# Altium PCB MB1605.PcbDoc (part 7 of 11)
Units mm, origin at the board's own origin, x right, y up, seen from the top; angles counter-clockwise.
Board outline 100 x 79.6 mm, 6 copper layers (Top Layer, Signal Layer 1, Signal Layer 2, Signal Layer 3, Signal Layer 4, Bottom Layer), stack 1.549 mm thick; 644 components, 529 nets, 2853 pads, 1462 vias.
Unrouted connection lines stored in the file: 2.
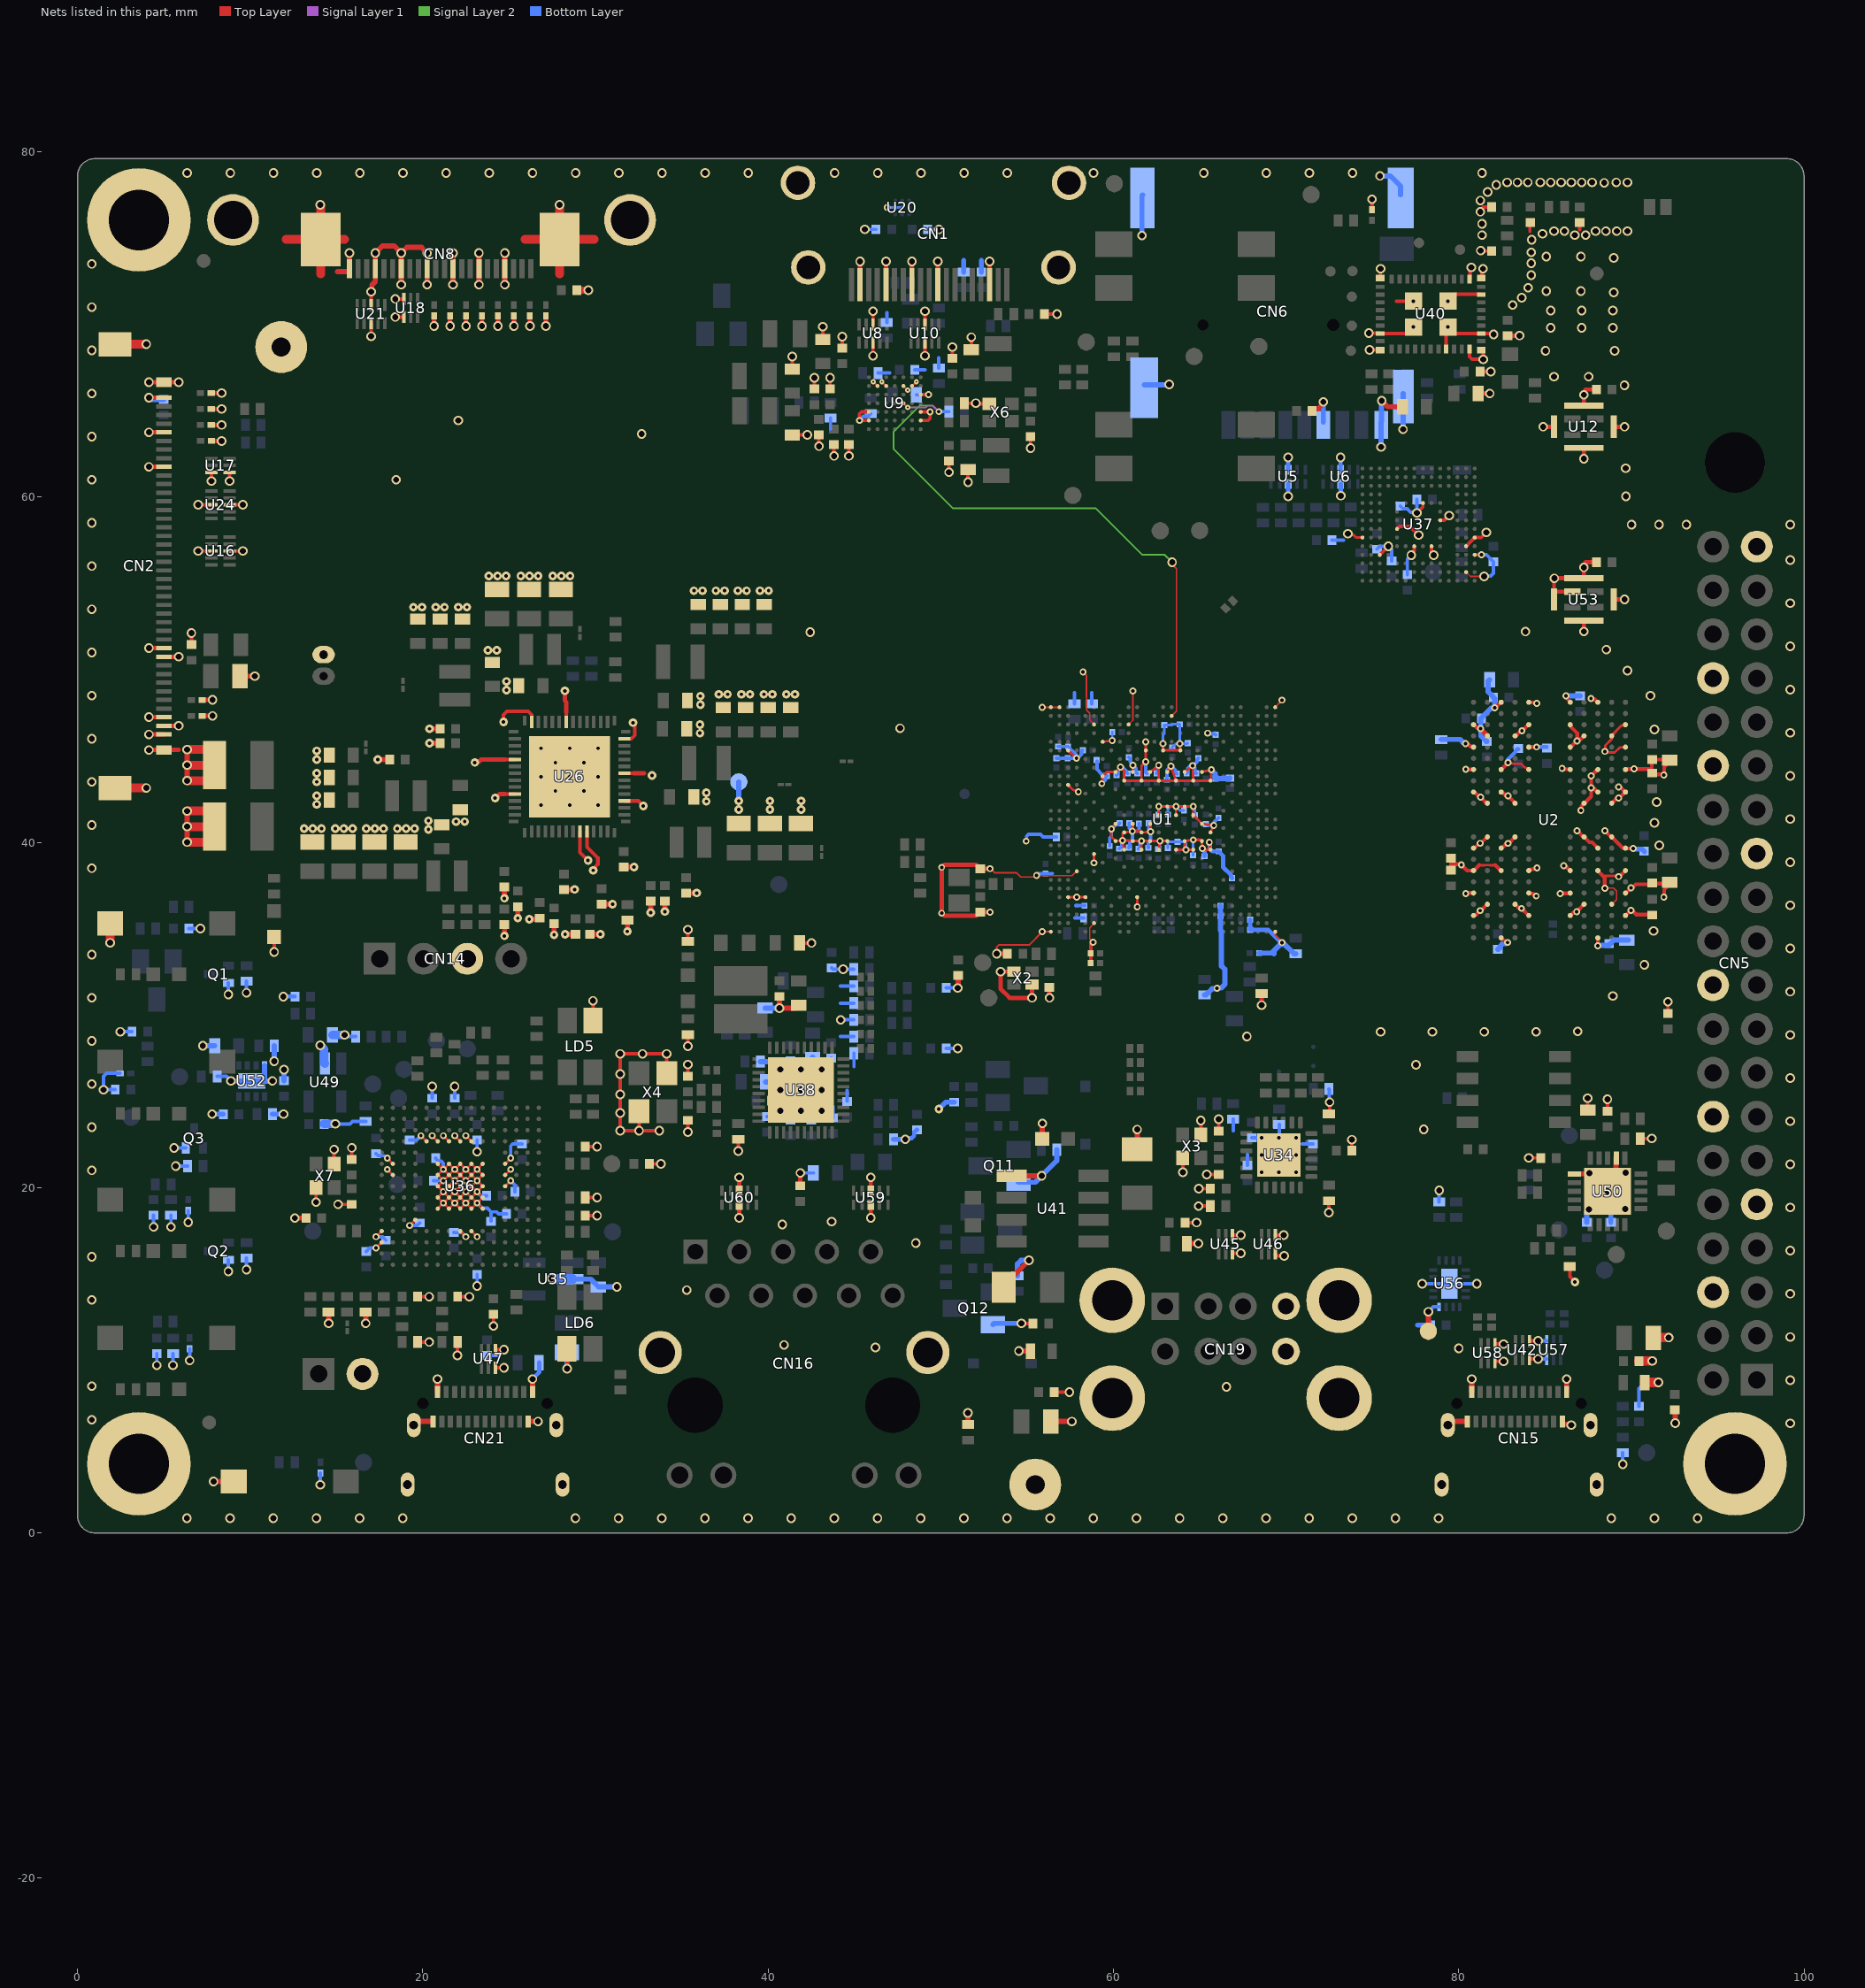
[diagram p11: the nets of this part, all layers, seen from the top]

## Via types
v1: diameter 0.55, hole 0.35, Top Layer to Bottom Layer, 823 vias
v2: diameter 0.4, hole 0.2, Top Layer to Bottom Layer, 235 vias
v3: diameter 0.4, hole 0.2, Top Layer to Bottom Layer, tented both sides, 216 vias
v4: diameter 0.5, hole 0.2, Top Layer to Bottom Layer, 159 vias
v5: diameter 0.25/0.3 (per signal layer), hole 0.1, Top Layer to Signal Layer 1, tented both sides, 29 vias

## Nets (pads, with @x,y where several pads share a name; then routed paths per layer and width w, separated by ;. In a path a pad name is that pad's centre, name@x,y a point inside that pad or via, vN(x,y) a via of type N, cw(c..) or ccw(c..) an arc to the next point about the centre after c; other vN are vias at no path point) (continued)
GND: B1.2 B2.1 C1.1 C2.1 C3.1 C4.2 C5.2 C6.2 C7.2 C8.2 C9.1 C10.1 C11.1 C12.2 C13.2 C14.2 C15.2 C16.2 C17.2 C18.2 C19.2 C20.2 C21.2 C22.1 C23.1 C24.1 C25.1 C26.1 C27.1 C28.1 C29.1 C30.1 C31.2 C32.1 C33.1 C34.1 C35.1 C36.1 C37.1 C38.1 C39.1 C40.1 C41.1 C42.2 C43.1 C44.2 C45.1 C46.1 C47.2 C48.1 C49.1 C50.1 C51.1 C52.1 C53.1 C54.1 C55.1 C56.1 C57.1 C58.1 C59.1 C60.1 C61.1 C62.2 C63.1 C64.1 C65.2 C66.1 C67.1 C68.1 C69.1 C70.2 C71.1 C72.1 C73.2 C74.1 C75.1 C76.1 C77.2 C78.2 C79.2 C80.2 C81.2 C82.1 C83.1 C84.1 C85.1 C86.2 C87.1 C88.1 C89.1 C90.1 C91.2 C92.2 C93.1 C96.2 C97.2 C98.2 C99.2 C101.1 C102.2 C103.1 C104.1 C105.2 C106.2 C107.2 C108.1 C109.1 C110.1 C111.1 C113.1 C114.1 C115.1 C116.1 C117.1 C118.1 C119.1 C120.1 C122.1 C123.1 C125.1 C126.1 C127.1 C128.1 C129.1 C130.1 C131.1 C132.1 C133.1 C134.1 C135.1 C136.1 C137.1 C139.1 C140.2 C141.1 C143.1 C145.1 C146.1 C147.2 C148.1 C149.1 C150.1 C151.1 C152.1 C155.1 C156.1 C157.2 C158.2 C159.1 C160.1 C161.1 C162.1 C163.1 C164.2 C165.1 C166.1 C167.1 C168.1 C169.1 C170.1 C171.1 C172.1 C173.1 C174.1 C175.1 C176.1 C177.1 C179.1 C180.1 C181.1 C182.1 C183.1 C184.1 C185.1 C186.1 C187.1 C188.1 C189.1 C190.2 C192.1 C193.1 C194.1 C195.1 C196.1 C197.1 C198.1 C199.1 C200.1 C201.1 C202.1 C203.1 C204.1 C205.1 C206.1 C207.1 C208.2 C209.1 C213.1 C214.2 C215.2 C216.1 C217.2 C218.1 C219.1 C220.1 C222.1 C223.1 C224.1 C225.1 C226.1 C227.1 C228.2 C229.2 C232.2 C233.1 C234.1 C235.1 C236.1 C237.1 C238.1 C239.1 C240.1 C244.1 C246.1 C248.1 C250.1 C251.1 C252.1 C253.1 C260.1 C280.2 C281.2 C282.2 C288.1 C289.2 C290.2 C295.1 C296.1 C297.2 C298.2 C299.2 C302.1 C303.2 C306.1 C309.1 C310.2 C311.2 C314.1 C317.1 C322.1 C323.1 C324.2 C325.2 C326.2 C327.2 C328.2 C329.2 C332.1 C333.2 C334.2 C335.2 CN1.2 CN1.5 CN1.8 CN1.11 CN1.17 CN1.20 CN1.21 CN1.22 CN1.23 CN2.1 CN2.5 CN2.9 CN2.30 CN2.31 CN2.38 CN2.39 CN2.40 CN2.41 CN2.42 CN2.43 CN2.44 CN5.6 CN5.9 CN5.14 CN5.20 CN5.25 CN5.30 CN5.34 CN5.39 CN6.6 CN6.9 CN6.11 CN6.12 CN6.13 CN6.14 CN8.1 CN8.4 CN8.7 CN8.10 CN8.13 CN8.16 CN8.19 CN8.S1 CN8.S2 CN12.2 CN14.3 CN15.A1 CN15.A12 CN15.B1 CN15.B12 CN15.SH1 CN15.SH2 CN15.SH3 CN15.SH4 CN16.15 CN16.16 CN19.B4 CN19.CH1 CN19.CH2 CN19.CH3 CN19.CH4 CN19.T4 CN21.A1 CN21.A12 CN21.B1 CN21.B12 CN21.SH1 CN21.SH2 CN21.SH3 CN21.SH4 JP3.2 LD4.2 LD5.3 LD6.3 LD11.2 pad.1@3.55,4 pad.1@3.55,76.05 pad.1@9,76.05 pad.1@32,76.05 pad.1@96,4 Q1.2 Q2.2 Q3.2 Q11.2 Q12.2 R1.1 R5.1 R6.2 R7.2 R15.2 R16.1 R17.1 R18.1 R23.2 R25.2 R26.1 R41.1 R42.1 R57.1 R97.1 R98.1 R99.1 R102.1 R106.1 R113.1 R128.1 R135.1 R137.1 R140.2 R141.1 R143.1 R151.2 R158.1 R194.2 R199.2 R200.1 R205.2 R213.2 R215.2 R220.1 R221.2 R222.2 R226.1 R229.1 R231.2 R234.1 R239.1 R242.2 R250.2 R251.2 R292.1 R293.1 R303.1 R304.1 R305.1 R322.1 R323.1 R324.1 R327.1 TP8.1 TP30.1 TP34.1 TP2000.1 U1.1A1 U1.1A3 U1.1A5 U1.1A7 U1.1A9 U1.1A11 U1.1B2 U1.1B4 U1.1B6 U1.1B8 U1.1B10 U1.1B12 U1.1E7 U1.1E9 U1.1F6 U1.1F8 U1.1F10 U1.1G1 U1.1G3 U1.1G5 U1.1G11 U1.1H2 U1.1H4 U1.1H12 U1.1J1 U1.1J3 U1.1J5 U1.1J7 U1.1J9 U1.1J11 U1.1K2 U1.1K4 U1.1K6 U1.1K8 U1.1K10 U1.1K12 U1.A1 U1.A2 U1.A27 U1.AC3 U1.AC5 U1.AC11 U1.AF6 U1.AG1 U1.AG27 U1.C6 U1.C10 U1.E7 U1.F3 U1.F12 U1.F14 U1.F16 U1.J7 U1.K3 U1.V6 U1.Y4 U2.A3 U2.A10 U2.AB3 U2.AB5 U2.AB8 U2.AB10 U2.C1 U2.C5 U2.C8 U2.C12 U2.D2 U2.D4 U2.D9 U2.D11 U2.E1 U2.E5 U2.E8 U2.E12 U2.G1 U2.G3 U2.G5 U2.G8 U2.G10 U2.G12 U2.J1 U2.J3 U2.J10 U2.J12 U2.K2 U2.K4 U2.K9 U2.K11 U2.N2 U2.N4 U2.N9 U2.N11 U2.P1 U2.P3 U2.P10 U2.P12 U2.T1 U2.T3 U2.T5 U2.T8 U2.T10 U2.T12 U2.V1 U2.V5 U2.V8 U2.V12 U2.W2 U2.W4 U2.W9 U2.W11 U2.Y1 U2.Y5 U2.Y8 U2.Y12 U3.2 U4.2 U5.3 U5.8 U6.3 U6.8 U7.2 U8.3 U8.8 U9.B2 U9.B3 U9.B5 U9.B6 U9.C7 U9.E1 U9.E7 U9.F1 U9.F7 U10.3 U10.8 U11.2 U12.5 U13.2 U14.2 U15.2 U16.3 U16.8 U17.3 U17.4 U18.3 U18.4 U19.2 U20.B2 U20.C2 U21.3 U21.8 U22.2 U23.2 U24.3 U24.8 U25.2 U26.9 U26.10 U26.18 U26.22 U26.27 U26.36 U26.41 U26.47 U26.52 U26.57 U27.2 U28.2 U29.2 U31.2 U32.2 U33.2 U34.25 U35.2 U36.D5 U36.D6 U36.D7 U36.D8 U36.D9 U36.F2 U36.F6 U36.F7 U36.F8 U36.F9 U36.F10 U36.F12 U36.G2 U36.G6 U36.G7 U36.G8 U36.G9 U36.G10 U36.G12 U36.H6 U36.H7 U36.H8 U36.H9 U36.H10 U36.H12 U36.J6 U36.J7 U36.J8 U36.J9 U36.J10 U36.K6 U36.K7 U36.K8 U36.K9 U36.K10 U36.L4 U36.M1 U36.M8 U36.M9 U36.N1 U37.A6 U37.C4 U37.E7 U37.G5 U37.H10 U37.J5 U37.K8 U37.N2 U37.N5 U37.P4 U37.P6 U38.41 U39.2 U40.1 U40.12 U40.19 U40.21 U40.29 U40.32 U40.33 U40.35 U40.40 U40.42 U40.43 U40.44 U40.45 U40.46 U41.1 U42.3 U42.4 U43.2 U44.2 U45.3 U45.4 U46.3 U46.4 U47.3 U47.4 U48.2 U49.2 U50.12 U50.16 U50.21 U51.2 U52.8 U52.9 U53.2 U53.5 U54.2 U56.3 U56.12 U56.18 U56.19 U57.3 U57.4 U58.3 U58.4 U59.3 U59.8 U60.3 U60.8 X2.2 X2.4 X3.2 X3.4 X4.2 X4.4 X6.2 X7.2 X7.4 | length 597.6
  Top Layer w0.09: v2(55.55,38.085) 55.565,38.07 56.266,38.07 56.271,38.075 57.612,38.075 57.862,38.325 U1.Y4@57.875,38.325 ; U1.A1@56.375,47.825 U1.A2@56.875,47.825 ; 58.445,48.418 58.445,47.647 58.625,47.467 58.625,47.075 U1.C6@58.875,46.825 ; v2(58.816,34.213) 58.625,34.404 58.625,35.05 58.875,35.3 U1.AF6@58.875,35.325 ; U1.C10@60.875,46.825 61.125,47.075 v2(61.125,48.775) ; U37.N2@80.425,55.655 80.675,55.405 v1(81.475,55.405) ; U2.T10@82.459,44.194 U2.T10@82.459,44.206 ; v2@82.859,44.607 82.859,44.619 v2@82.937,44.619 ; v2@86.859,40.669 86.872,40.669 v2@86.884,40.669 ; U2.K4@87.234,40.319 U2.K4@87.259,40.319 ; v2@88.459,37.344 88.467,37.352 88.976,37.352 89.145,37.183 89.145,36.68 U2.D2@88.859,36.394
  Top Layer w0.1: v2(52.85,38.475) 52.882,38.475 53.114,38.244 54.372,38.244 54.622,37.994 55.458,37.994 v2(55.55,38.085) ; v1(53.242,33.546) 53.242,33.945 53.355,34.058 55.108,34.058 v3(55.875,34.825) U1.AG1@56.375,34.825 ; v3(55.875,47.825) U1.A1@56.375,47.825 ; v2(58.24,49.865) 58.445,49.66 58.445,48.418 ; U1.AG27@69.37,34.82 69.37,34.64 69.768,34.241 v2(69.768,34.197) ; U1.A27@69.375,47.825 69.762,48.213 v3(69.762,48.238) ; v2(83.66,46.465) 83.685,46.465 v2@83.723,46.503 ; U2.Y8@84.035,46.815 U2.Y8@84.06,46.815 ; U2.V8@84.06,45.515 84.064,45.519 U2.V8@84.084,45.519 ; v2@84.505,45.519 v2(84.509,45.523)
  Top Layer w0.125: v2@82.974,44.57 83.12,44.57 83.144,44.545 83.616,44.545 83.835,44.326 83.9,44.326 84.018,44.208 U2.T8@84.018,44.194
  Top Layer w0.13: v5(46.086,66.685) U9.B2@46.336,66.435 ; v5(46.586,66.685) U9.B3@46.836,66.435 ; U9.B5@47.836,66.435 v5(48.086,66.185) ; U9.B6@48.336,66.435 v5(48.586,66.685)
  Top Layer w0.15: v3(17.29,16.507) U36.N1@17.615,16.832 ; v3(17.29,17.157) U36.M1@17.615,17.482 ; v3(17.94,21.057) U36.G2@18.265,20.732 ; v3(17.94,21.707) U36.F2@18.265,21.382 ; v3(19.24,17.807) U36.L4@19.565,18.132 ; v3(19.89,23.007) U36.D5@20.215,22.682 ; v3(20.54,23.007) U36.D6@20.865,22.682 ; U36.K6@20.865,18.782 v3(21.19,19.107) ; U36.F6@20.865,21.382 v3(21.19,21.057) ; v3(21.19,23.007) U36.D7@21.515,22.682 ; v3(21.84,23.007) U36.D8@22.165,22.682 ; U36.M8@22.165,17.482 v3(22.49,17.157) ; v3(22.49,23.007) U36.D9@22.815,22.682 ; U36.M9@22.815,17.482 v3(23.14,17.157) ; U36.K10@23.465,18.782 v3(23.14,19.107) ; U36.F10@23.465,21.382 v3(23.14,21.057) ; U36.H12@24.765,20.082 v3(25.09,20.407) ; U36.G12@24.765,20.732 v3(25.09,21.057) ; U36.F12@24.765,21.382 v3(25.09,21.707) ; U1.AC3@57.375,36.825 v3(57.875,36.825) U1.AC5@58.375,36.825 ; U1.K3@57.375,43.325 57.643,43.057 v3(57.966,42.92) ; U1.F3@57.375,45.325 v3(57.862,44.875) ; v3(58.868,38.812) 58.875,38.819 U1.V6@58.875,39.325 ; v3@59.325,43.275 59.35,43.3 59.35,43.613 ; v3(59.325,43.4) 59.35,43.613 ; U1.E7@59.375,45.825 v3(59.931,45.892) ; U1.J7@59.388,43.812 U1.J7@59.375,43.825 ; v3@59.862,40.821 v3(59.884,40.766) ; U1.1G1@60.125,41.075 v3(59.884,40.766) ; U1.1K2@60.625,39.575 v3(60.525,40.1) ; U1.1G3@61.125,41.075 v3(61.092,40.638) ; U1.1A3@61.125,44.075 v3(61.132,44.466) ; v3(61.375,36.265) U1.AC11@61.375,36.825 ; U1.1K4@61.625,39.575 v3(61.625,40.089) ; v3(61.875,45.825) U1.F12@61.875,45.325 v3(61.875,44.675) 61.625,44.425 U1.1B4@61.625,43.575 ; U1.1G5@62.125,41.075 v3(62.15,40.625) U1.1H4@61.625,40.575 61.562,40.638 v3(61.092,40.638) ; U1.1A5@62.125,44.075 v3(62.622,44.455) U1.1B6@62.625,43.575 ; U1.1K6@62.625,39.575 v3(62.7,40.075) ; U1.1F6@62.637,41.587 U1.1F6@62.625,41.575 ; v3(62.875,45.725) U1.F14@62.875,45.325 U1.F16@63.875,45.325 v3@63.853,45.725 ; U1.1J7@63.125,40.075 v3(62.7,40.075) ; U1.1A7@63.125,44.075 v3(63.328,44.412) U1.1B8@63.625,43.575 ; U1.1E7@63.137,42.062 U1.1E7@63.125,42.075 ; U1.1K8@63.625,39.575 v3(64.198,39.575) U1.1K10@64.625,39.575 ; U1.1F8@63.625,41.575 v3(63.625,42.075) ; U1.1A9@64.125,44.075 v3(64.586,44.446) U1.1B10@64.625,43.575 ; U1.1A11@65.125,44.075 v3(65.675,44.2) U1.1B12@65.625,43.575 U1.1B10@64.625,43.575 ; U1.1H12@65.625,40.575 v3(65.806,40.972) U1.1G11@65.125,41.075 U1.1F10@64.625,41.575 v3(64.625,42.075) U1.1E9@64.125,42.075 v3(63.625,42.075) ; v1(73.575,57.875) 73.646,57.804 73.911,57.804 74.056,57.66 74.42,57.66 U37.A6@74.425,57.655 ; U37.P4@80.925,56.655 v2(81.325,56.655) ; 81.193,38.681 81.527,38.681 81.531,38.684 81.791,38.684 81.795,38.681 82.106,38.681 ; v2@82.937,44.619 82.937,44.609 82.974,44.572 v2@82.974,44.57 ; U2.T8@84.018,44.194 U2.T8@84.059,44.194 ; 88.348,38.055 88.724,38.055 88.729,38.05 89.228,38.05 v2@89.259,38.019 ; U2.W2@88.859,46.169 88.859,46.196 89.433,46.77 89.562,46.77 U2.Y1@89.608,46.816 ; U2.W2@88.86,46.168 88.843,46.151 88.843,45.957 88.495,45.609 88.495,45.298 88.45,45.253 88.486,45.217 88.711,45.217 88.729,45.2 89.033,45.2 89.334,45.501 U2.V1@89.652,45.501 ; v3(21.19,19.107) U36.J7@21.515,19.432 ; v3(21.19,19.107) U36.J6@20.865,19.432 v3(21.19,19.757) ; v3(21.19,19.107) U36.K7@21.515,18.782 v3(21.84,19.107) ; v3(21.19,19.757) U36.H7@21.515,20.082 ; v3(21.19,19.757) U36.H6@20.865,20.082 v3(21.19,20.407) ; v3(21.19,19.757) U36.J7@21.515,19.432 ; v3(21.19,20.407) U36.G7@21.515,20.732 ; v3(21.19,20.407) U36.G6@20.865,20.732 v3(21.19,21.057) ; v3(21.19,20.407) U36.H7@21.515,20.082 ; v3(21.19,21.057) U36.F7@21.515,21.382 v3(21.84,21.057) ; v3(21.19,21.057) U36.G7@21.515,20.732 ; U36.J7@21.515,19.432 v3(21.84,19.757) ; U36.J7@21.515,19.432 v3(21.84,19.107) ; U36.H7@21.515,20.082 v3(21.84,20.407) ; U36.H7@21.515,20.082 v3(21.84,19.757) ; U36.G7@21.515,20.732 v3(21.84,21.057) ; U36.G7@21.515,20.732 v3(21.84,20.407) ; v3(21.84,19.107) U36.J8@22.165,19.432 ; v3(21.84,19.107) U36.K8@22.165,18.782 v3(22.49,19.107) ; v3(21.84,19.757) U36.H8@22.165,20.082 ; v3(21.84,19.757) U36.J8@22.165,19.432 ; v3(21.84,20.407) U36.G8@22.165,20.732 ; v3(21.84,20.407) U36.H8@22.165,20.082 ; v3(21.84,21.057) U36.F8@22.165,21.382 v3(22.49,21.057) ; v3(21.84,21.057) U36.G8@22.165,20.732 ; U36.J8@22.165,19.432 v3(22.49,19.757) ; U36.J8@22.165,19.432 v3(22.49,19.107) ; U36.H8@22.165,20.082 v3(22.49,20.407) ; U36.H8@22.165,20.082 v3(22.49,19.757) ; U36.G8@22.165,20.732 v3(22.49,21.057) ; U36.G8@22.165,20.732 v3(22.49,20.407) ; v3(22.49,19.107) U36.J9@22.815,19.432 ; v3(22.49,19.107) U36.K9@22.815,18.782 v3(23.14,19.107) ; v3(22.49,19.757) U36.H9@22.815,20.082 ; v3(22.49,19.757) U36.J9@22.815,19.432 ; v3(22.49,20.407) U36.G9@22.815,20.732 ; v3(22.49,20.407) U36.H9@22.815,20.082 ; v3(22.49,21.057) U36.F9@22.815,21.382 v3(23.14,21.057) ; v3(22.49,21.057) U36.G9@22.815,20.732 ; U36.J9@22.815,19.432 v3(23.14,19.757) ; U36.J9@22.815,19.432 v3(23.14,19.107) ; U36.H9@22.815,20.082 v3(23.14,20.407) ; U36.H9@22.815,20.082 v3(23.14,19.757) ; U36.G9@22.815,20.732 v3(23.14,21.057) ; U36.G9@22.815,20.732 v3(23.14,20.407) ; v3(23.14,19.107) U36.J10@23.465,19.432 v3(23.14,19.757) ; v3(23.14,19.757) U36.H10@23.465,20.082 v3(23.14,20.407) ; v3(23.14,20.407) U36.G10@23.465,20.732 v3(23.14,21.057) ; 59.35,43.613 59.35,43.825 U1.J7@59.375,43.825 ; 59.35,43.613 U1.J7@59.375,43.825 ; U1.J7@59.375,43.825 59.625,44.075 U1.1A1@60.125,44.075 60.133,44.075 60.408,44.35 v3(60.408,44.353) 60.625,44.136 U1.1B2@60.625,43.575 U1.1B4@61.625,43.575 ; v3(59.884,40.766) 59.884,40.316 U1.1J1@60.125,40.075 v3(60.525,40.1) ; v3(60.525,40.1) 60.525,40.475 U1.1H2@60.625,40.575 v3(61.092,40.638) ; v3(60.525,40.1) 61.1,40.1 U1.1J3@61.125,40.075 v3(61.625,40.089) ; v3(61.625,40.089) U1.1J5@62.125,40.075 v3(62.7,40.075) ; U1.1B4@61.625,43.575 U1.1B6@62.625,43.575 ; U1.1F6@62.625,41.575 v3(62.625,42.075) ; U1.1F6@62.625,41.575 v3(62.625,42.075) ; v3(62.625,42.075) U1.1E7@63.125,42.075 ; U1.1B6@62.625,43.575 U1.1B8@63.625,43.575 ; U1.1E7@63.125,42.075 v3@63.625,42.075 ; U1.1B8@63.625,43.575 U1.1B10@64.625,43.575
  Top Layer w0.16: v3(64.198,39.575) 64.125,39.648 U1.1J9@64.125,40.075 v3(64.625,40.143) 65.057,40.143 U1.1J11@65.125,40.075 v3(65.15,39.65) 65.225,39.575 U1.1K12@65.625,39.575 v3(65.55,40)
  Top Layer w0.2: C93.1@6.596,51.449 v1(6.596,52.124) ; v1(6.985,56.875) U16.3@7.752,56.875 ; v1(6.985,59.55) U24.3@7.752,59.55 ; v1(7.752,60.926) U17.3@7.752,61.425 ; U16.8@8.802,56.875 v1(9.569,56.875) ; U24.8@8.802,59.55 v1(9.569,59.55) ; v1(8.802,60.926) U17.4@8.802,61.425 ; v1(11.386,33.645) LD11.2@11.386,34.522 ; v1(13.815,19.162) X7.2@13.815,20.007 ; v1(14.86,22.207) 14.86,21.362 X7.4@14.865,21.357 ; v1(15.09,19.032) C140.2@15.885,19.032 ; C133.1@15.885,21.632 v1(15.885,22.307) ; v1(17,69.308) U21.8@17,70.075 ; U21.3@17,71.125 v1(17,71.892) ; v1(18.401,70.425) U18.4@18.9,70.425 ; v1(18.401,71.475) U18.3@18.9,71.475 ; R221.2@19.695,11.057 v1(20.37,11.057) ; C157.2@19.695,13.682 v1(20.37,13.682) ; v1(22,10.287) 22.007,10.295 22.007,11.05 R222.2@22.015,11.057 ; C158.2@22.015,13.682 v1(22.69,13.682) ; v1(24.09,11.982) C160.1@24.09,12.657 ; U47.3@24.2,9.561 v1(24.699,9.561) ; U47.4@24.2,10.611 v1(24.699,10.611) ; v1(28.35,9.519) LD6.3@28.35,10.669 ; C145.1@29.415,18.382 v1(30.09,18.382) ; R194.2@29.415,19.432 v1(30.09,19.432) ; C132.1@29.415,22.382 v1(30.09,22.382) ; LD5.3@29.858,29.675 v1(29.858,30.825) ; U26.27@31.67,46 32.079,46 32.27,46.191 32.27,46.91 v4@32.316,46.956 ; v4(32.17,46.93) v4@32.227,46.873 ; X4.2@32.525,24.425 v1(32.525,23.3) ; C131.1@33.115,21.382 v1(33.79,21.382) ; v1(33.7,23.3) v1(32.525,23.3) ; X4.4@34.125,26.625 v1(34.125,27.75) v1(32.725,27.75) v1(31.425,27.75) v1(31.425,26.575) v1(31.425,25.4) v1(31.425,24.325) v1(31.425,23.3) v1(32.525,23.3) ; v1(35.35,23.225) C223.1@35.35,23.9 ; C222.1@35.35,26.45 v1(35.35,27.125) ; v1(35.35,28.195) R158.1@35.35,28.87 ; R151.2@35.35,34.27 v1(35.35,34.945) ; v1(38.275,22.125) R199.2@38.275,22.8 ; C98.2@41.4,63.599 v1(42.27,63.599) ; C78.2@41.4,67.416 v1(41.4,68.143) ; C111.1@41.82,34.17 v1(42.515,34.17) ; C122.1@42.689,66.256 v1@42.689,66.907 ; v1@42.943,62.948 C139.1@42.943,63.599 ; C79.2@43.164,69.136 v1(43.164,69.863) ; C101.1@43.589,66.256 v1@43.589,66.907 ; v1@43.815,62.384 C125.1@43.815,63.035 ; C102.2@44.3,68.636 v1@44.3,69.287 ; v1@44.676,62.384 C113.1@44.676,63.035 ; v2@45.292,64.43 v2(45.292,64.435) ; U9.F1@45.836,64.435 v2(45.292,64.435) ; U9.E1@45.836,64.935 45.409,64.935 45.292,64.818 v2(45.292,64.435) ; v1(46.072,68.182) U8.8@46.072,68.948 ; U8.3@46.072,69.998 v1(46.072,70.765) ; U9.F7@48.836,64.435 49.263,64.435 49.38,64.552 v2@49.38,64.935 ; U9.E7@48.836,64.935 v2@49.38,64.935 ; U9.C7@48.836,65.935 v2(49.286,65.935) ; v1(49.079,68.182) U10.8@49.079,68.948 ; U10.3@49.079,69.998 v1(49.079,70.765) ; v2(49.38,64.94) v2@49.38,64.935 ; v1@50.471,61.442 C107.2@50.471,62.092 ; C108.1@50.676,68.032 v1@50.676,68.683 ; R26.1@51.376,65.435 v1@52.026,65.435 ; v1(51.579,60.865) C96.2@51.579,61.592 ; C97.2@51.769,68.532 v1(51.769,69.259) ; v1@52.148,65.395 X6.2@52.813,65.395 ; v1(54.67,12.136) C227.1@55.345,12.136 ; v1@55.196,62.844 C182.1@55.196,63.495 ; C179.1@56.003,70.6 v1(56.73,70.6) ; C146.1@56.559,8.16 v1(57.446,8.16) ; C248.1@58.683,33.002 C250.1@58.683,33.572 58.683,34.08 v2(58.816,34.213) ; X3.4@64.018,21.715 64.025,21.708 v1(64.025,20.888) ; C155.1@64.14,17.976 v1(64.815,17.976) ; v1(64.936,18.934) 65.613,18.934 R97.1@65.619,18.927 ; v1(64.94,19.937) 65.616,19.937 C114.1@65.623,19.931 ; v1(65.064,23.889) 65.064,23.069 X3.2@65.068,23.065 X3.2@65.071,23.062 ; v1(65.405,20.758) 66.082,20.758 C119.1@66.088,20.752 ; C1.1@66.088,23.276 66.095,23.282 v1(66.095,23.959) ; U45.3@66.9,16.2 v1(67.375,16.2) ; U45.4@66.9,17.25 v1(67.375,17.25) ; U46.3@69.384,16.2 69.384,16.045 v1(69.889,16.045) ; U46.4@69.384,17.25 v1(69.859,17.25) ; v1(72.477,18.554) 72.477,19.231 R323.1@72.483,19.237 ; R324.1@72.477,24.267 72.521,24.311 v1(72.521,24.948) ; v1(73.816,22.778) 73.819,22.775 C127.1@73.819,22.14 ; v1(74.8,69.5) 74.814,69.486 75.439,69.486 U40.19@75.45,69.475 77,69.475 v4(77.375,69.85) ; v1(74.836,68.523) 74.841,68.518 75.445,68.518 U40.21@75.45,68.513 ; U37.C4@75.425,56.655 75.875,57.105 75.885,57.105 v1(75.925,57.145) ; U40.12@75.45,72.687 75.463,72.7 75.463,73.213 v1(75.475,73.225) ; 76.4,71.35 v4(77.375,71.35) ; U37.E7@76.425,58.155 76.575,58.305 77.17,58.305 v1(77.675,57.8) ; v1(77.25,56.63) 77.25,56.718 77.425,56.893 U37.G5@77.425,57.155 ; v1(77.575,59.08) 77.925,59.43 U37.H10@77.925,59.655 ; U37.J5@78.425,57.155 78.425,56.85 78.55,56.725 v1(78.55,56.63) ; U37.K8@78.925,58.655 79.175,58.655 v1(79.45,58.93) ; U40.29@79.275,68.575 79.275,69.75 v4(79.375,69.85) 79.75,69.475 U40.35@81.3,69.475 81.963,69.475 v1(82.019,69.419) ; v4(79.375,71.35) 79.775,71.75 80.378,71.75 80.772,71.75 81.275,71.75 U40.40@81.3,71.725 ; U37.N5@80.425,57.155 U37.P6@80.925,57.655 81.305,57.655 v1(81.6,57.95) ; U40.32@80.625,68.575 80.625,68.125 80.775,67.975 v1(81.425,67.975) 81.425,68.425 81.338,68.513 U40.33@81.3,68.513 ; U40.1@80.625,72.625 80.65,72.65 80.65,73.13 80.725,73.205 v1(80.725,73.3) ; U2.J12@80.86,39.665 80.914,39.665 81.164,39.915 81.247,39.915 81.648,40.315 U2.K11@81.66,40.315 ; U40.42@81.3,72.687 81.353,72.74 81.353,73.175 v1(81.406,73.228) ; 81.425,76.8 C175.1@81.9,76.8 ; v1@81.475,74.25 C167.1@81.9,74.25 ; U58.3@82.1,9.888 82.1,9.938 v1(82.6,9.938) ; U58.4@82.1,10.938 v1(82.599,10.938) ; v1(84.063,21.723) C168.1@84.738,21.723 ; U42.3@84.1,10.073 v1(84.599,10.073) ; U42.4@84.1,11.123 v1(84.599,11.123) ; 84.125,75.375 84.125,75.875 C174.1@84.15,75.9 ; U53.5@85.525,54.07 85.525,55.282 v1(85.538,55.295) ; R327.1@86.438,15.425 86.438,14.833 v4(86.734,14.536) ; 87,75.5 C176.1@87,75.9 ; C170.1@87.463,24.503 v1(87.463,25.178) ; U50.21@87.613,20.798 U50.21@88.613,19.798 ; C171.1@88.613,24.448 v1(88.613,25.123) ; R231.2@90.513,22.848 v1(91.188,22.848) ; C232.2@92.118,30.09 v1(92.118,30.765)
  Top Layer w0.21: v4(24.675,46.975) 24.675,47.375 24.88,47.58 26.109,47.58 26.3,47.389 U26.41@26.3,46.97 ; 24.775,42.8 U26.52@25.33,42.8 ; 24.775,44.8 U26.47@25.33,44.8 ; U26.36@28.3,46.97 28.3,47.525 ; U26.9@29.1,40.63 29.1,39.42 v4(29.568,38.952) ; U26.10@29.5,40.63 29.5,39.734 30.135,39.099 30.135,38.72 29.87,38.456 v4(29.87,38.377) ; U26.18@31.67,42.4 32.472,42.4 v4(32.772,42.1) ; U26.22@31.67,44 32.225,44
  Top Layer w0.22: C5.2@79.559,38.379 79.559,38.729 ; C13.2@79.559,39.079 79.559,38.729 ; v2@80.151,38.625 v2@80.2,38.625 ; v2(80.4,45.719) 80.527,45.719 80.693,45.554 80.765,45.554 80.788,45.53 80.85,45.53 U2.V12@80.86,45.521 ; v2(80.41,37.025) 80.45,37.065 U2.E12@80.86,37.065 ; v2@80.425,44.215 U2.T12@80.86,44.215 ; U2.G12@80.83,38.38 U2.G12@80.845,38.365 ; U2.G12@80.854,38.356 U2.G12@80.845,38.365 ; U2.P12@80.859,42.894 80.874,42.879 80.949,42.879 81.149,42.679 81.17,42.679 81.293,42.556 81.293,42.535 81.347,42.535 81.637,42.244 U2.N11@81.659,42.244 ; U2.C12@80.86,35.765 80.875,35.78 80.975,35.78 v2(81.24,36.045) 81.288,36.045 U2.D11@81.658,36.415 ; U2.G12@80.86,38.365 U2.G12@80.845,38.365 ; U2.Y12@80.86,46.815 80.882,46.815 81.073,46.623 81.236,46.623 v2(81.271,46.589) ; U2.G12@80.87,38.36 81.19,38.681 81.193,38.681 ; v2(82.085,47.79) 82.113,47.79 82.438,48.115 U2.AB10@82.46,48.115 ; 82.106,38.681 82.378,38.409 82.399,38.409 82.452,38.356 U2.G10@82.456,38.356 ; U2.A10@82.459,34.444 82.465,34.45 82.496,34.45 82.716,34.229 82.799,34.229 v2@82.833,34.195 ; U2.J10@82.459,39.644 82.481,39.644 82.721,39.885 82.825,39.885 82.859,39.919 82.872,39.919 83.247,40.294 U2.K9@83.259,40.294 ; U2.P10@82.459,42.894 82.474,42.879 82.557,42.879 82.842,42.594 v2@82.897,42.594 ; U2.T10@82.459,44.206 v2@82.859,44.606 ; v2(82.86,42.69) 82.859,42.677 83.259,42.277 U2.N9@83.259,42.265 ; U2.W9@83.259,46.144 83.281,46.144 83.571,46.435 83.625,46.435 83.693,46.503 v2@83.723,46.503 ; U2.D9@83.26,36.415 83.5,36.175 v2(83.635,36.175) ; v2@83.641,36.175 U2.C8@84.059,35.756 ; v2@83.747,46.503 v2@83.723,46.503 ; U2.Y8@84.035,46.815 v2@83.723,46.503 ; U2.E8@84.059,37.044 84.074,37.029 84.301,37.029 84.435,36.894 v2@84.484,36.894 ; U2.G8@84.059,38.365 84.081,38.365 84.16,38.444 84.336,38.444 84.372,38.481 84.497,38.481 v2@84.534,38.444 ; U2.AB8@84.06,48.115 84.075,48.1 84.421,48.1 84.466,48.054 v2(84.515,48.054) ; U2.V8@84.072,45.506 U2.V8@84.084,45.519 ; U2.V8@84.088,45.523 U2.V8@84.084,45.519 ; v2@84.505,45.519 U2.V8@84.084,45.519 ; v2@85.885,37.04 85.891,37.046 86.384,37.046 86.388,37.05 86.445,37.05 U2.E5@86.46,37.065 ; v2(85.99,44.285) 86.039,44.285 86.093,44.23 86.445,44.23 U2.T5@86.46,44.215 ; v2(86.085,38.64) 86.118,38.606 86.197,38.606 U2.G5@86.446,38.356 ; v2(86.21,48.489) 86.244,48.455 86.244,48.352 86.46,48.137 U2.AB5@86.46,48.115 ; U2.C5@86.459,35.744 86.461,35.744 86.663,35.946 86.791,35.946 U2.D4@87.26,36.415 ; U2.V5@86.46,45.515 86.482,45.515 86.832,45.865 v2(86.86,45.865) v2@86.86,45.988 ; U2.Y5@86.46,46.815 86.475,46.8 86.475,46.716 86.86,46.331 v2@86.86,45.988 ; v2@86.8,35.946 v2(86.835,35.981) ; v2@86.872,40.669 87.247,40.294 U2.K4@87.259,40.294 ; v2(87.075,41.85) 87.109,41.884 87.109,42.093 U2.N4@87.26,42.243 ; U2.K4@87.259,40.315 87.57,40.004 87.72,40.004 U2.J3@88.059,39.665 ; U2.N4@87.26,42.265 U2.N4@87.26,42.243 ; U2.W4@87.26,46.165 87.083,45.988 v2@86.86,45.988 ; v2(87.661,48.325) 87.695,48.291 87.863,48.291 88.038,48.115 U2.AB3@88.06,48.115 ; v2@87.678,43.153 87.715,43.116 87.838,43.116 88.038,42.915 U2.P3@88.06,42.915 ; v2@88.059,33.994 U2.A3@88.059,34.444 ; U2.G3@88.059,38.344 88.348,38.055 88.459,37.944 v2@88.459,37.344 ; U2.T3@88.06,44.215 88.04,44.215 v2(87.675,43.85) v2(87.675,43.15) 87.675,42.658 U2.N4@87.26,42.243 ; v2@88.459,40.669 88.472,40.669 88.847,40.294 U2.K2@88.859,40.294 ; U2.N2@88.859,42.244 89.15,42.535 89.225,42.535 v2@89.259,42.569 ; U2.K2@88.86,40.315 89.531,39.644 89.659,39.644 v2@90.109,39.644 ; v2@89.259,38.019 89.293,38.053 89.347,38.053 89.637,38.344 U2.G1@89.659,38.344 ; v2@89.259,43.219 89.334,43.219 U2.P1@89.638,42.915 ; v2(89.26,42.565) 89.288,42.565 U2.P1@89.638,42.915 ; U2.C1@89.659,35.744 89.954,36.039 v2@89.954,36.147 ; U2.E1@89.659,37.044 89.672,37.044 89.972,37.344 90.033,37.344 90.258,37.569 C7.2@91.159,37.569 ; U2.P1@89.659,42.894 U2.P1@89.638,42.915 ; U2.T1@89.659,44.194 U2.T1@89.681,44.194 ; U2.T1@89.659,44.244 C14.2@91.184,44.244 ; U2.P1@89.66,42.915 U2.P1@89.638,42.915 ; v2@90.033,36.069 90.033,36.066 90.068,36.031 90.071,36.031 90.283,35.819 C15.2@91.159,35.819 ; C7.2@91.159,37.694 C7.2@91.247,37.606 ; C7.2@91.245,37.606 92.095,37.606 C3.1@92.183,37.519 ; C14.2@91.263,43.939 91.85,43.939 v2(91.884,43.904) 91.899,43.92 91.899,44.36 92.083,44.544 91.833,44.794 91.184,44.794 C14.2@91.184,44.244 ; C14.2@91.264,43.939 91.184,44.019 C14.2@91.184,44.244 ; v2(91.884,36.829) 91.899,36.844 91.899,37.255 92.138,37.494 92.233,37.494 C3.1@92.208,37.519 ; 79.559,38.729 80.121,38.729 v2(80.15,38.7) 80.485,38.365 U2.G12@80.845,38.365
  Top Layer w0.25: v1(4.135,45.35) CN2.43@5,45.35 5.865,45.35 ; v1(4.135,46.25) CN2.40@5,46.25 ; v1(4.135,47.25) CN2.38@5,47.25 ; v1(4.135,51.25) CN2.30@5,51.25 ; v1(4.135,61.75) CN2.9@5,61.75 ; v1(4.135,63.75) CN2.5@5,63.75 ; v1(4.135,65.75) CN2.1@5,65.75 ; v1(4.135,66.65) CN2.42@5,66.65 v1(5.865,66.65) ; CN2.39@5,46.75 v1(5.865,46.75) ; CN2.31@5,50.75 v1(5.865,50.75) ; U23.2@7.221,47.325 v1(7.819,47.325) ; U22.2@7.221,48.25 v1(7.819,48.25) ; U3.2@7.742,63.25 U3.2@7.754,63.25 v1(8.339,63.25) ; U13.2@7.742,64.175 v1(8.339,64.175) ; U7.2@7.742,65.1 v1(8.339,65.1) ; U4.2@7.742,66.025 v1(8.339,66.025) ; v1(20.65,69.903) U11.2@20.65,70.501 ; v1(21.575,69.903) U29.2@21.575,70.501 ; v1(22.5,69.903) U31.2@22.5,70.501 ; v4(23.008,44.625) 23.056,44.673 23.257,44.673 23.384,44.8 24.775,44.8 ; v1(23.425,69.903) U14.2@23.425,70.501 ; v4(24.187,42.563) 24.221,42.563 24.459,42.8 24.775,42.8 ; v1(24.35,69.903) U32.2@24.35,70.501 ; v1(25.275,69.903) U33.2@25.275,70.501 ; v1(26.2,69.903) U19.2@26.2,70.501 ; v1(27.125,69.903) U39.2@27.125,70.501 ; v4(28.225,48.775) 28.225,48.214 28.3,48.139 28.3,47.525 ; 32.225,44 32.83,44 ; v4@32.757,42.1 v4(32.772,42.1) ; v1(38.325,18.245) U60.8@38.325,19.012 ; U60.3@38.325,19.832 v1(38.325,20.599) ; C152.1@41.865,20.109 v1(41.865,20.85) ; CN1.2@45.326,72.3 v1(45.326,73.65) ; v1(45.945,18.245) U59.8@45.945,19.012 ; U59.3@45.945,19.832 v1(45.945,20.599) ; CN1.5@46.826,72.3 v1(46.826,73.65) ; CN1.8@48.326,72.3 v1(48.326,73.65) ; CN1.11@49.826,72.3 v1(49.826,73.65) ; CN1.17@52.826,72.3 v1(52.826,73.65) ; v2(52.85,35.95) C86.2@52.285,35.95 52.26,35.95 52.061,35.75 50.196,35.75 v2(50.05,35.897) v2(50.05,38.554) 50.196,38.7 52.06,38.7 C81.2@52.285,38.475 v2(52.85,38.475) ; v1(53.242,33.546) C92.2@53.859,33.546 ; X2.2@54.234,32.51 v1(53.467,32.51) 53.467,31.513 53.987,30.993 v1(55.284,30.993) X2.4@55.284,31.76 ; v1(56.293,30.993) C90.1@56.293,31.61 ; v1(68.584,30.569) R6.2@68.584,31.233 ; U54.2@74.975,76.65 v1(74.975,77.248) ; C135.1@81.128,66 81.13,66.003 v1(81.798,66.003) ; C134.1@81.23,67.262 v1(81.859,67.262) ; C137.1@82.84,69.35 v1(83.52,69.35) ; v1(84.896,64.07) U12.5@85.525,64.07 ; v1(85.538,55.295) U53.5@87.25,55.295 v1(87.25,55.924) ; U53.5@85.621,54.52 U53.2@86.575,54.52 ; v1(87.25,52.216) U53.5@87.25,52.845 ; v1(87.25,62.216) U12.5@87.25,62.845 ; U12.5@87.25,65.295 v1(87.25,65.924) ; 87.346,56.231 C229.2@87.975,56.231 ; 87.346,66.231 C228.2@87.975,66.231 ; U53.5@88.975,54.07 v1(89.604,54.07) ; U12.5@88.975,64.07 v1(89.604,64.07)
  Top Layer w0.3: v1(6.347,40.012) v1(6.347,40.912) v1(6.347,41.812) ; v1(6.347,43.574) v1(6.347,44.474) v1(6.347,45.374) ; v1(7.877,2.979) B1.2@9.049,2.979 ; C85.1@9.414,49.625 v1(10.264,49.625) ; v1(12.586,18.239) C149.1@13.231,18.239 ; v1(14.54,12.137) R213.2@14.54,12.782 ; 15.055,73.058 15.75,73.058 CN8.1@15.75,73.222 v1(15.75,74.139) ; v1(16.69,12.137) R215.2@16.69,12.782 ; v1(17,71.892) 17.045,71.937 17.045,72.272 17.25,72.477 CN8.4@17.25,73.222 v1(17.25,74.139) 17.655,74.544 18.345,74.544 v1(18.75,74.139) ; v4(17.395,44.79) C43.1@18.055,44.79 ; v1(18.75,72.305) CN8.7@18.75,73.222 v1(18.75,74.139) ; CN21.SH1@19.47,6.25 19.68,6.46 CN21.B12@20.6,6.46 ; v1(20.25,72.305) v1(20.25,74.139) 19.92,74.469 19.08,74.469 v1(18.75,74.139) ; v4(20.385,45.75) C40.1@20.995,45.75 ; v4(20.385,46.575) C39.1@20.995,46.575 ; CN21.A1@20.85,8.16 v1(20.85,8.913) ; v1(21.75,72.305) CN8.13@21.75,73.222 v1(21.75,74.139) ; v1(23.25,72.305) CN8.16@23.25,73.222 v1(23.25,74.139) ; v4@24.725,36.81 C217.2@24.725,37.42 ; v4(24.727,34.58) C219.1@24.727,35.185 ; v1(24.75,72.305) CN8.19@24.75,73.222 v1(24.75,74.139) ; v4(25.5,35.61) C216.1@25.5,36.215 ; CN21.B1@26.1,6.46 CN21.B1@26.1,6.46 26.669,6.458 v1(26.671,6.456) ; v4(26.165,35.55) C215.2@26.775,35.55 ; CN21.A12@26.35,8.16 v1(26.35,8.913) ; v4@27.6,34.69 C214.2@27.6,35.3 ; C213.1@28.175,37.27 v4(28.785,37.27) ; v4(28.24,34.68) C91.2@28.85,34.68 ; C208.2@29.675,34.68 v4(30.285,34.68) ; C209.1@30.35,36.42 v4(30.985,36.42) ; C61.1@31.625,38.57 v4(32.235,38.57) ; v4(31.85,34.84) R57.1@31.85,35.5 ; v4(33.2,35.93) C189.1@33.2,36.59 ; v4(34.025,35.99) C188.1@34.025,36.59 C188.1@34.025,36.65 ; C190.2@35.25,37.065 v4(35.86,37.065) ; C123.1@40.65,31.075 v1(40.65,30.4) 41.6,30.4 C120.1@41.775,30.575 ; v1(50.979,31.565) 51,31.586 C33.1@51,32.3 ; R234.1@51.575,6.275 v1(51.575,6.95) ; C226.1@53.645,14.225 53.645,14.415 54.195,14.965 54.275,14.965 v1(55.103,15.792) ; U41.1@54.104,20.683 55.841,20.683 v1(55.843,20.681) ; v1(54.525,10.535) U51.2@55.195,10.535 ; LD4.2@55.876,22.826 55.876,23.714 v1(55.887,23.725) ; C143.1@56.37,6.456 v1(57.59,6.456) ; C150.1@61.375,22.222 v1(61.375,23.367) ; U44.2@64.25,16.76 v1(64.92,16.76) ; C218.1@71.51,64.99 71.51,65.015 71.615,65.12 71.859,65.12 72.112,65.373 72.112,65.463 v1(72.16,65.511) ; v1(75.54,65.576) 75.886,65.231 C136.1@76.732,65.231 ; TP34.1@78.243,11.686 v1(78.243,12.811) ; CN15.SH1@79.37,6.25 79.58,6.46 CN15.B12@80.5,6.46 ; v2(80.41,44.23) v2@80.425,44.215 ; CN15.A1@80.75,8.16 v1(80.75,8.913) ; v2(81.271,46.589) 81.271,46.562 81.66,46.173 U2.W11@81.66,46.165 ; CN15.B1@86,6.46 86,6.298 86.475,6.298 v1(86.522,6.25) ; CN15.A12@86.25,8.16 v1(86.25,8.913) ; U50.16@86.688,20.798 87.538,20.798 v1(87.575,20.835) ; v1(88.625,19.785) 89.113,20.273 U50.12@89.113,21.723 ; v1(92.536,6.357) C233.1@92.536,7.133
  Top Layer w0.4: C224.1@28.925,71.975 v1@29.575,71.975
  Top Layer w0.5: v1(1.886,34.182) B2.1@1.886,35.3 ; CN2.44@2.63,43.15 v1(3.982,43.15) ; CN2.41@2.63,68.85 v1(3.982,68.85) ; v1@6.353,40.006 C147.2@7.936,40.006 ; v1@6.353,40.906 C147.2@7.936,40.906 ; v1@6.353,41.818 C147.2@7.936,41.818 ; v1@6.353,43.568 C42.2@7.936,43.568 ; v1@6.353,44.468 C42.2@7.936,44.468 ; v1@6.353,45.38 C42.2@7.936,45.38 ; 12.074,74.922 CN8.S1@14.08,74.922 ; v1@14.079,76.912 14.072,76.905 14.08,76.897 CN8.S1@14.08,74.922 ; 14.08,72.916 CN8.S1@14.08,74.922 ; 15.468,74.922 CN8.S1@14.08,74.922 ; 25.914,74.922 CN8.S2@27.92,74.922 ; 27.92,72.916 CN8.S2@27.92,74.922 ; v1(27.92,76.932) CN8.S2@27.92,74.922 ; 29.926,74.922 CN8.S2@27.92,74.922
  Top Layer w0.55: C156.1@90.437,9.965 v1(91.212,9.965) ; U43.2@90.763,8.715 v1(91.562,8.715) ; C159.1@91.262,11.315 v1(92.163,11.315)
  Bottom Layer w0.1: C8.2@83.458,45.395 83.458,45.443 C8.2@83.46,45.445
  Bottom Layer w0.15: v2(46.897,76.769) U20.C2@47.364,76.769 U20.B2@47.764,76.769 ; v3(59.931,45.892) 59.935,45.896 C205.1@59.935,46.38 ; C57.1@62.592,39.603 62.683,39.694 62.683,40.058 v3(62.7,40.075) 63.066,40.075 63.154,39.987 C60.1@63.154,39.672 ; C55.1@62.6,41.6 62.6,42.05 v3(62.625,42.075) ; v3(62.875,45.725) 62.875,46.219 62.95,46.294 C195.1@62.95,46.787 63.379,46.787 63.429,46.837 C239.1@63.85,46.837 ; 63.134,40.036 C59.1@63.714,40.036 64.111,40.036 64.198,39.949 v3(64.198,39.575) ; C52.1@63.162,41.607 63.162,41.944 63.293,42.075 v3(63.625,42.075) 63.844,41.856 C53.1@64.083,41.856 ; C67.1@63.4,45.5 63.586,45.686 63.807,45.686 v3@63.859,45.738 ; v3(63.85,45.725) 64.278,45.725 C69.1@64.305,45.752 ; v3@63.85,45.775 C239.1@63.85,46.787 ; C58.1@64.607,39.247 64.607,40.125 v3(64.625,40.143) ; v3(64.625,42.075) 64.706,41.994 C54.1@64.706,41.579 ; C82.1@65.352,41.053 65.433,40.972 v3(65.806,40.972)
  Bottom Layer w0.2: C163.1@2.183,25.673 v1(1.508,25.673) 1.508,26.443 1.691,26.627 U28.2@2.458,26.627 ; v1(2.481,29.032) C87.1@3.156,29.032 ; v1(4.406,17.725) C161.1@4.406,18.4 ; v1(4.592,9.713) C162.1@4.592,10.388 ; v1(5.413,17.725) R128.1@5.413,18.4 ; v1(5.532,9.713) R135.1@5.532,10.388 ; v1(5.588,22.302) Q3.2@6.263,22.302 ; v1(5.688,21.252) R137.1@6.363,21.252 ; v1(6.413,18) U25.2@6.413,18.675 ; C88.1@6.442,35.008 v1(7.117,35.008) ; v1(6.493,9.988) U27.2@6.493,10.663 ; R140.2@8.077,26.441 8.622,26.441 v1(8.886,26.177) ; v1(8.736,15.152) Q2.2@8.736,15.827 ; v1(8.736,31.186) Q1.2@8.736,31.861 ; v1(9.786,15.252) R141.1@9.786,15.927 ; v1(9.786,31.286) R143.1@9.786,31.961 ; v1(14.062,2.79) U15.2@14.062,3.465 ; v1(14.935,23.691) 15.774,23.691 15.926,23.844 R229.1@16.69,23.844 ; v1(15.463,28.847) 15.56,28.75 R226.1@16.115,28.75 ; C327.2@16.715,16.307 16.915,16.507 v3(17.29,16.507) ; v3(17.29,17.157) 17.665,17.157 C281.2@17.865,16.957 ; C324.2@17.29,21.975 17.416,21.849 17.744,21.849 17.886,21.707 v3(17.94,21.707) ; v3(19.24,17.807) 19.665,17.807 C299.2@19.815,17.957 ; C289.2@19.24,22.757 19.64,22.757 v3(19.89,23.007) ; C282.2@20.54,25.182 v1(20.54,25.857) ; C298.2@20.615,20.407 v3(21.19,20.407) ; C310.2@20.74,21.707 20.74,21.682 20.895,21.527 21.073,21.527 21.19,21.41 v3(21.19,21.057) ; C326.2@21.79,17.407 21.803,17.394 22.253,17.394 v3(22.49,17.157) ; C297.2@21.84,25.182 v1(21.84,25.857) ; v1(23.14,14.307) C325.2@23.14,14.982 ; v3(23.14,19.107) 23.442,18.805 23.738,18.805 23.945,18.599 ; v3(23.14,19.757) 23.365,19.532 C329.2@23.69,19.532 ; v1(23.14,22.082) C290.2@23.14,22.757 ; C164.2@23.71,10.287 24.375,10.287 v1(24.699,10.611) ; C333.2@23.945,18.057 23.945,18.599 ; C303.2@24.84,18.482 24.393,18.482 24.276,18.599 23.945,18.599 ; v3(25.09,20.407) 25.34,20.157 C328.2@25.34,19.757 ; v3(25.09,21.707) 25.09,22.415 25.207,22.532 C311.2@25.74,22.532 ; C309.1@39.945,24.12 40.37,24.12 v1(40.7,24.45) ; C306.1@40.2,25.05 40.825,25.05 ; C322.1@41.3,23.925 41.3,24.55 ; 41.3,26.725 C296.1@41.3,27.35 ; v1(41.865,20.85) C332.1@42.625,20.85 ; C323.1@42.5,23.925 42.5,24.55 ; 43.613,63.925 R25.2@43.613,64.579 ; 43.65,26.689 C295.1@43.65,27.5 ; C104.1@43.675,32.726 43.751,32.65 v1(44.345,32.65) R305.1@44.969,32.65 ; C317.1@43.75,24.05 43.75,24.675 ; 44.201,28.755 44.206,28.75 R113.1@44.97,28.75 ; v1(44.2,29.72) R292.1@44.97,29.72 ; 44.201,30.688 R293.1@44.97,30.688 ; 44.201,31.67 R304.1@44.97,31.67 ; C314.1@44.575,25 44.575,25.625 ; 44.97,27.016 R303.1@44.97,27.785 ; v2(45.292,64.435) 45.528,64.671 45.787,64.671 R17.1@45.942,64.826 ; v1@45.601,75.504 C180.1@46.252,75.504 ; R16.1@46.374,67.181 47.028,67.181 ; R18.1@46.875,70.103 46.875,70.687 ; C106.2@48.495,67.364 49.079,67.364 ; C80.2@48.595,65.92 49.272,65.92 v2(49.286,65.935) ; C181.1@49.243,75.504 v1@49.893,75.504 ; R23.2@49.887,67.475 49.887,68.058 ; C103.1@50.309,31.565 v1(50.979,31.565) ; C141.1@50.31,28.065 v1(50.979,28.065) ; v2(54.943,40.07) 54.967,40.094 54.967,40.353 55.085,40.47 55.765,40.47 55.926,40.309 C225.1@56.696,40.309 ; v2(55.55,38.085) 55.663,38.198 C234.1@56.064,38.198 56.461,38.198 ; C237.1@56.696,44.88 C236.1@57.345,44.88 ; C192.1@56.8,45.55 C201.1@57.375,45.55 57.825,45.1 57.825,44.912 v3(57.862,44.875) 57.862,44.894 57.881,44.914 57.974,44.914 58.163,45.103 58.163,45.282 C197.1@58.216,45.334 ; C236.1@57.35,44.875 v3(57.862,44.875) ; R250.2@57.744,48.02 57.744,48.67 ; 57.781,35.625 C235.1@58.275,35.625 ; 57.831,36.331 C244.1@58.325,36.331 ; R251.2@58.751,48.02 58.751,48.67 ; C240.1@59.05,44.7 59.05,44.225 59.344,43.931 59.534,43.931 C220.1@59.609,43.856 59.534,43.781 59.534,43.609 v3(59.325,43.4) ; C70.2@59.78,39.785 59.78,40.268 59.884,40.372 v3(59.884,40.766) 60.148,41.03 60.276,41.03 C44.2@60.351,41.105 ; C45.1@60.173,43.895 60.248,43.97 60.248,44.139 60.408,44.299 v3(60.408,44.353) 60.419,44.342 60.54,44.342 60.739,44.143 60.739,44.063 C51.1@60.814,43.988 ; C71.1@60.34,39.635 60.491,39.786 60.491,40.066 v3(60.525,40.1) ; C196.1@60.9,44.925 60.975,44.85 60.975,44.677 61.132,44.52 v3(61.132,44.466) ; C72.1@60.905,39.698 60.956,39.749 60.956,40.021 61.092,40.157 v3(61.092,40.638) ; C46.1@60.915,41.105 60.915,40.815 v3(61.092,40.638) ; v3@61.169,44.408 61.302,44.274 61.302,44.062 C49.1@61.377,43.987 ; C73.2@61.467,39.624 61.542,39.699 61.542,39.952 61.625,40.035 v3(61.625,40.089) ; C47.2@61.476,41.081 61.476,40.694 61.42,40.638 v3(61.092,40.638) ; v3(61.875,44.675) 61.875,44.054 C50.1@61.941,43.988 ; C74.1@62.03,39.683 62.03,39.955 62.15,40.075 v3(62.15,40.625) 62.038,40.737 C48.1@62.038,41.107 ; C63.1@62.506,44.005 62.581,44.08 62.581,44.36 62.622,44.401 v3(62.622,44.455) ; C62.2@63.106,43.628 63.106,44.19 v3(63.328,44.412) 63.366,44.374 63.421,44.374 63.6,44.195 63.6,44.059 C65.2@63.675,43.984 ; C68.1@64.239,43.997 64.314,44.072 64.314,44.284 64.437,44.408 64.548,44.408 v3(64.586,44.446) ; C64.1@64.8,43.996 64.725,44.071 64.725,44.307 v3(64.586,44.446) ; C66.1@64.915,44.871 64.84,44.796 64.84,44.663 64.623,44.446 v3(64.586,44.446) ; v3(65.46,46.325) 65.498,46.287 65.852,46.287 C238.1@65.913,46.226 ; v3(65.806,40.972) 65.844,41.01 65.844,41.178 C75.1@66.083,41.417 ; 66.934,23.294 R102.1@66.934,23.959 ; C116.1@67.757,21.305 67.757,21.921 ; C115.1@68.021,22.888 v2(68.587,22.888) v2@68.637,22.888 ; v2@69.6,22.985 R99.1@69.6,23.65 ; 70.936,22.538 C126.1@71.552,22.538 ; R98.1@72.477,25.712 72.499,25.69 72.499,24.97 v1(72.521,24.948) ; C89.1@72.65,57.5 73.315,57.5 ; C118.1@75.26,56.98 75.425,57.145 v1(75.925,57.145) 76.11,56.96 C148.1@76.11,56.305 ; C9.1@76.615,59.48 76.77,59.325 77.008,59.325 77.208,59.126 77.529,59.126 v1(77.575,59.08) C117.1@77.575,59.864 ; C130.1@77.027,55.505 77.027,56.407 v1(77.25,56.63) ; v1(77.887,14.436) U56.3@78.528,14.436 U56.19@79.468,14.436 U56.12@80.408,14.436 v1(81.049,14.436) ; v1(78.243,12.811) 78.528,13.096 U56.18@78.868,13.096 ; R106.1@78.868,19.165 v1(78.868,19.84) ; v2(81.325,56.655) 81.615,56.655 C128.1@82.015,56.255 82.015,55.592 81.858,55.435 81.505,55.435 v1(81.475,55.405) ; v1(84.599,10.073) U57.3@85.098,10.073 ; v1(84.599,11.123) U57.4@85.098,11.123 ; v1(89.5,3.975) R220.1@89.5,4.65 ; C99.2@90.437,7.329 90.437,8.365 90.787,8.715 v1(91.562,8.715)
  Bottom Layer w0.22: v1(11.922,31.068) C25.1@12.592,31.068 ; v2@82.824,44.755 82.813,44.765 83.29,45.242 83.29,45.3 83.385,45.395 C8.2@83.458,45.395 ; v2@82.858,44.62 82.892,44.654 v2@82.892,44.782 ; v2@84.508,45.528 84.51,45.53 C21.2@85.108,45.53
  Bottom Layer w0.25: v1(26.35,8.913) 26.735,9.298 U48.2@26.735,9.865 ; v1(47.945,22.8) 48.002,22.857 48.312,22.857 48.459,23.004 48.459,23.215 48.589,23.345 C109.1@48.614,23.345 ; v3(65.15,39.65) 65.274,39.526 C76.1@65.274,39.198 ; v3(65.55,40) 65.579,39.971 65.579,39.627 65.725,39.48 66.095,39.48 C77.2@66.1,39.475 66.35,39.225 66.35,38.57 66.82,38.1 66.82,37.985 C252.1@66.87,37.935 ; C246.1@67.925,35.525 C253.1@67.925,34.925 68.975,34.925 v2@69.666,34.234 ; v1(70.125,60.042) U5.8@70.125,60.762 ; U5.3@70.125,61.582 v1(70.125,62.302) ; U6.8@73.154,60.762 73.165,60.752 73.165,60.085 v1(73.175,60.075) ; U6.3@73.154,61.582 v1(73.154,62.302)
  Bottom Layer w0.3: v1(4.135,65.75) 4.23,65.75 4.33,65.65 C84.1@4.979,65.65 ; v1(7.259,28.217) C169.1@7.936,28.217 ; v1(7.791,24.257) C172.1@8.436,24.257 ; v1(8.886,26.177) U52.9@10.086,26.177 U52.9@10.685,26.177 ; U52.8@10.836,27.077 10.836,26.328 U52.9@10.685,26.177 ; v1(11.284,26.177) U52.9@10.685,26.177 ; R239.1@11.286,24.257 v1(11.931,24.257) ; v1(11.386,27.327) R242.2@11.386,28.217 ; C173.1@11.961,26.186 v1(11.961,26.831) ; v1@28.346,9.519 C110.1@28.346,10.463 ; U35.2@28.646,14.7 29.72,14.7 C129.1@30.17,14.25 v1(31.239,14.25) ; v4(38.304,42.401) TP30.1@38.304,43.502 ; R322.1@39.55,27.3 40.375,27.3 ; C280.2@39.825,30.4 v1(40.65,30.4) ; C302.1@39.85,26.125 40.675,26.125 ; 42.575,26.725 C288.1@42.575,27.55 ; R205.2@47.27,22.8 v1(47.945,22.8) ; v4(49.889,24.55) 50.289,24.95 C105.2@50.775,24.95 ; R15.2@51.33,73.025 51.33,73.69 ; C177.1@52.35,73.025 52.35,73.69 ; Q12.2@53.022,12.063 53.096,12.136 v1(54.67,12.136) ; R200.1@54.438,14.887 54.438,15.577 54.653,15.792 v1(55.103,15.792) ; Q11.2@54.5,20.313 55.474,20.313 v1(55.843,20.681) 56.725,21.564 R41.1@56.725,22.2 ; v1(61.65,75.15) 61.65,77.465 CN6.12@61.685,77.5 ; CN6.13@61.785,66.5 63.2,66.5 v1(63.225,66.525) ; R7.2@65.274,31.173 65.369,31.173 65.723,31.527 65.984,31.527 v2(66.003,31.546) 66.023,31.565 66.243,31.565 66.449,31.771 66.449,32.645 66.258,32.836 66.258,34.855 66.2,34.914 C260.1@66.2,35.714 C151.1@66.2,36.324 ; v3@65.694,44.181 65.694,44.168 65.888,43.974 65.888,43.723 C83.1@65.913,43.698 66.723,43.698 R1.1@66.75,43.725 ; C251.1@68.44,33.588 69.159,33.588 ; 69.3,33.641 69.3,33.546 69.258,33.588 69.159,33.588 ; v2@69.749,34.09 v2@69.749,34.178 ; R5.1@70.555,33.546 70.46,33.546 69.828,34.178 69.787,34.178 v2(69.768,34.197) v2@69.749,34.178 ; CN6.6@72.16,64.35 v1(72.16,65.511) ; v1(75.435,78.6) 76.035,78.6 76.635,78 CN6.11@76.635,77.5 ; v1(75.5,62.9) 75.51,62.91 CN6.9@75.51,64.175 75.51,64.35 75.525,64.365 75.525,65.561 v1(75.54,65.576) ; v1(76.775,63.925) 76.775,65.99 CN6.14@76.785,66 ; 77.63,12.039 C31.2@78.368,12.039 ; R42.1@78.984,45.96 80.086,45.96 80.286,45.759 v2@80.313,45.759 ; v2@81.24,46.526 81.278,46.564 C12.2@81.278,47.154 ; 81.279,46.373 81.298,46.354 81.298,46.157 81.603,45.852 C4.2@81.628,45.852 ; C12.2@81.309,47.185 C12.2@81.278,47.154 ; C10.1@81.784,49.42 81.708,49.343 81.708,48.72 82.024,48.404 C16.2@82.024,48.379 ; C16.2@81.983,48.42 C16.2@82.024,48.379 ; v2@82.083,47.795 82.083,48.32 C16.2@82.024,48.379 ; v2(82.085,47.79) 82.066,47.77 81.87,47.77 81.278,47.179 C12.2@81.278,47.154 ; C19.2@82.259,33.81 82.284,33.81 82.389,33.915 82.389,33.967 82.565,34.143 82.74,34.143 82.797,34.2 v2(82.83,34.2) ; v2(86.21,48.489) 86.213,48.492 87.031,48.492 C17.2@87.034,48.495 ; C334.2@87.413,17.997 87.413,18.598 v1(87.55,18.735) ; v2@88.058,33.995 88.092,34.03 88.667,34.03 88.733,34.095 88.758,34.095 89.008,34.345 C11.1@89.833,34.345 ; C335.2@88.813,17.997 88.813,18.735 ; v2@90.059,39.645 90.108,39.645 90.142,39.611 90.617,39.611 C20.2@90.758,39.47 ; 69.159,33.588 v2@69.749,34.178
  Bottom Layer w0.5: v1(14.062,28.25) 14.062,28.236 14.281,28.017 14.281,27.243 U49.2@14.331,27.193 ; C166.1@14.29,23.691 v1(14.935,23.691) ; C165.1@14.763,28.847 v1(15.463,28.847)
  Bottom Layer w0.6: v1(27.467,14.747) 27.514,14.7 U35.2@28.646,14.7
  other v1: 6.336,0.85 8.836,0.85 11.336,0.85 13.836,0.85 16.336,0.85 18.836,0.85 28.836,0.85 31.336,0.85 33.836,0.85 36.336,0.85 38.836,0.85 41.336,0.85 43.836,0.85 46.336,0.85 48.836,0.85 51.336,0.85 53.836,0.85 56.336,0.85 58.836,0.85 61.336,0.85 63.836,0.85 66.336,0.85 68.836,0.85 71.336,0.85 73.836,0.85 76.336,0.85 78.836,0.85 88.836,0.85 91.336,0.85 93.836,0.85 99.2,6.35 0.825,6.55 66.546,8.463 0.825,8.5 99.2,8.85 80.003,10.689 46.217,10.747 40.926,10.891 99.2,11.35 0.825,13.5 99.2,13.85 35.29,14.067 0.825,16 99.2,16.35 48.554,16.79 40.825,17.867 43.675,18.033 89.65,18.76 99.2,18.85 89.675,20.86 0.825,21 99.2,21.35 77.975,23.375 0.825,23.5 99.2,23.85 41.9,24.45 43.1,24.45 40.7,25.65 41.9,25.65 43.1,25.65 0.825,26 99.2,26.35 40.7,26.85 41.9,26.85 43.1,26.85 77.524,27.113 0.825,28.5 67.73,28.759 99.2,28.85 75.479,29.025 78.479,29.025 81.479,29.025 84.479,29.025 86.895,29.055 0.825,31 88.932,31.104 99.2,31.35 90.755,32.906 0.825,33.5 99.2,33.85 91.285,34.865 99.2,36.35 0.825,38.5 99.2,38.85 91.617,39.829 0.825,41 91.339,41.128 99.2,41.35 91.467,42.332 0.825,43.5 99.2,43.85 0.825,46 99.2,46.35 91.339,46.544 47.642,46.608 0.825,48.5 91.101,48.492 99.2,48.85 89.772,49.948 0.825,51 88.551,51.167 99.2,51.35 42.433,52.177 83.87,52.208 0.825,53.5 99.2,53.85 0.825,56 99.2,56.35 90.012,58.404 91.6,58.405 93.188,58.406 99.2,58.406 0.825,58.5 89.687,60.041 0.825,61 18.454,61 50.476,61.437 89.674,61.665 43.82,62.379 44.68,62.379 55.201,62.839 42.948,62.943 0.825,63.5 32.673,63.658 22.05,64.434 52.031,65.44 0.825,66 89.6,66.475 42.684,66.912 43.584,66.912 85.525,66.975 87.525,66.975 85.025,68.475 89.025,68.475 0.825,68.5 50.671,68.688 44.295,69.292 85.325,69.8 87.125,69.8 88.925,69.8 85.325,70.8 87.125,70.8 88.925,70.8 0.825,71 83.125,71.125 83.65,71.55 88.975,71.85 85.075,71.925 87.075,71.925 29.58,71.98 84.025,72.125 84.2,72.85 0.825,73.5 84.2,73.55 88.975,73.85 85.075,73.925 87.075,73.925 84.2,74.175 81.275,74.275 84.225,74.9 81.35,75.175 86.725,75.175 87.35,75.175 84.85,75.25 85.525,75.4 86.125,75.4 87.925,75.4 88.525,75.4 89.15,75.4 89.775,75.4 49.898,75.499 45.596,75.509 81.35,75.825 81.25,76.525 14.062,76.928 81.25,77.175 81.675,77.675 82.175,78.075 88.425,78.2 82.8,78.225 83.4,78.225 84,78.225 84.725,78.225 85.325,78.225 85.925,78.225 86.525,78.225 87.125,78.225 87.725,78.225 89.125,78.225 89.775,78.225 6.35,78.775 8.85,78.775 11.35,78.775 13.85,78.775 16.35,78.775 18.85,78.775 21.35,78.775 23.85,78.775 26.35,78.775 28.85,78.775 31.35,78.775 33.85,78.775 36.35,78.775 38.85,78.775 43.85,78.775 46.35,78.775 48.85,78.775 51.35,78.775 53.85,78.775 58.85,78.775 65.234,78.775 68.85,78.775 71.35,78.775 73.85,78.775 81.35,78.775
  other v2: 68.587,20.888 69.587,20.888 70.587,20.888 68.587,21.888 69.587,21.888 70.587,21.888 69.587,22.888 70.587,22.888 88.06,34.015 89.985,36.065 84.485,36.89 85.885,37.04 88.46,37.34 89.985,37.365 89.26,38.015 84.535,38.515 90.11,39.64 82.86,39.94 81.235,39.945 86.86,40.665 88.46,40.665 81.26,42.625 89.26,43.215 90.16,44.265 82.86,44.615 88.46,45.265
  other v4: 27.6,34.64 24.725,36.76 20.325,40.75 13.124,40.798 13.625,40.798 14.126,40.798 14.924,40.798 15.425,40.798 15.926,40.798 16.724,40.798 17.225,40.798 17.726,40.798 18.524,40.798 19.025,40.798 19.526,40.798 21.924,41.202 22.425,41.202 20.325,41.25 38.304,41.9 40.104,41.9 41.904,41.9 26.85,42.15 28.5,42.15 30.15,42.15 13.85,42.2 36.42,42.375 40.104,42.401 41.904,42.401 13.85,42.7 36.42,42.875 27.675,42.975 29.325,42.975 13.85,43.5 26.85,43.8 28.5,43.8 30.15,43.8 33.28,43.875 13.85,44 27.675,44.625 29.325,44.625 13.85,44.8 13.85,45.3 26.85,45.45 28.5,45.45 30.15,45.45 36.05,46.325 36.05,46.825 36.075,47.975 36.075,48.475 37.15,48.575 37.65,48.575 38.45,48.575 38.95,48.575 39.75,48.575 40.25,48.575 41.05,48.575 41.55,48.575 24.85,48.823 24.85,49.323 23.775,51.123 24.276,51.123 19.45,53.623 19.951,53.623 20.75,53.623 21.251,53.623 22.05,53.623 22.551,53.623 35.7,54.575 36.2,54.575 36.975,54.575 37.475,54.575 38.25,54.575 38.75,54.575 39.525,54.575 40.025,54.575 23.824,55.425 24.325,55.425 24.826,55.425 25.674,55.425 26.175,55.425 26.676,55.425 27.524,55.425 28.025,55.425 28.526,55.425
HDMI.INT: R13.2 U1.B15 U9.D5 | length 35.3
  Top Layer w0.09: U1.B15@63.375,47.325 63.65,47.6 63.65,48.575
  Top Layer w0.097: 63.65,48.575 63.65,48.681
  Top Layer w0.1: v1(63.4,56.225) 63.4,56.106 63.65,55.856 63.65,48.681
  Top Layer w0.13: U9.D5@47.836,65.435 v5(48.086,65.185)
  Signal Layer 1 w0.1: v5(48.086,65.185) 49.13,65.185 49.235,65.29 49.546,65.29 v2(49.889,64.947)
  Signal Layer 2 w0.1: v2(49.889,64.947) 49.546,65.29 48.769,65.29 47.267,63.787 47.267,62.78 50.702,59.345 58.979,59.345 61.286,57.038 61.671,56.653 62.972,56.653 v1(63.4,56.225)
  Bottom Layer w0.2: v2(49.889,64.947) R13.2@50.476,64.947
